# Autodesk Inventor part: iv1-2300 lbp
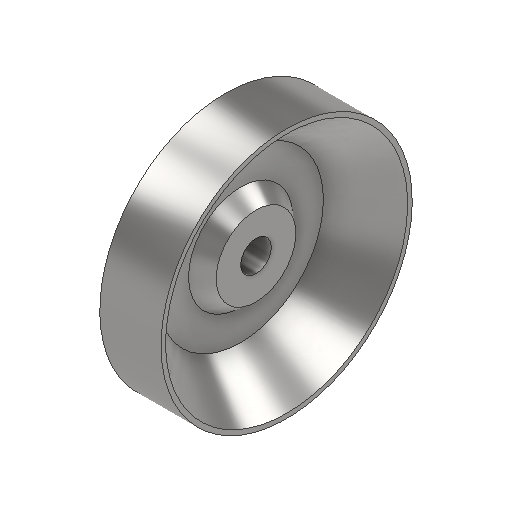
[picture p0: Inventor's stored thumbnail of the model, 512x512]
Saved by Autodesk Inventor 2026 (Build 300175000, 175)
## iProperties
Created: 2022-01
Part Number: iv1-2300 lbp
Material: Steel, Mild
Document SubType Name: Modeling
Designer: Lars Bertram Pedersen
Density: 7.85 g/cm^3
Appearance: Semi-Polished
Mass: 54634.2 g
Surface Area: 4391.39 cm^2
Volume: 6959.77 cm^3
Author: Lars Bertram Pedersen
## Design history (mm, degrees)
revolve "Revolution1" stored, may be unused: angle "d8" = 90 deg
body "Solid1"
sketch "Sketch1"
  geometry: L1 (0, 0)-(100, 0); L2 (0, 25)-(0, 205); L3 (0, 205)-(100, 205); L4 (100, 197.5)-(25, 135); L5 (25, 135)-(25, 85); L6 (25, 85)-(50, 65); L7 (50, 65)-(50, 25); L8 (50, 25)-(0, 25); L9 (100, 205)-(100, 197.5)
  constraints: 18 end point, 3 vertical, 2 horizontal, 2 vertical alignment, 1 parallel, 1 perpendicular
  dimensions: "d0" = 100 distance of L1.start L1.end; "d1" = 410 diameter of L3 L1; "d2" = 270 diameter of L4.end L1; "d3" = 170 diameter of L5.end L1; "d4" = 50 distance of L7.end L2.start; "d5" = 50 diameter of L8 L1; "d6" = 130 diameter of L6.end L1; "d7" = 25 distance between parallel lines of L5 L2; "d9" = 395 diameter of L4.start L1
